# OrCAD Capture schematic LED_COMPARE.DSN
size C
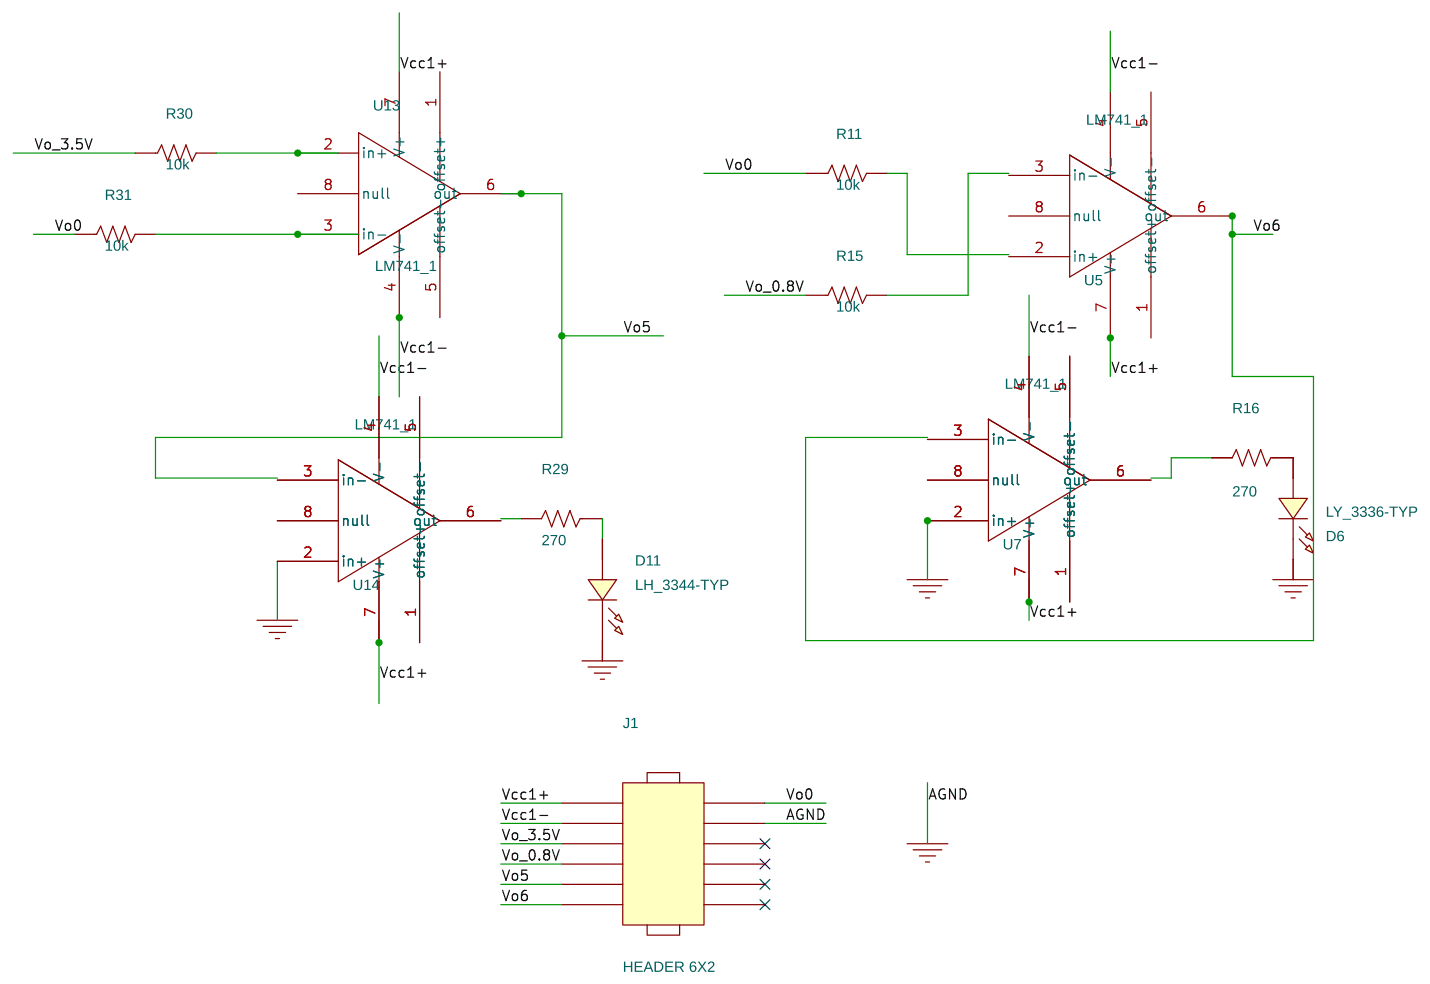
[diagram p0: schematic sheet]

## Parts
D6  LY_3336-TYP  [fg]
D11  LH_3344-TYP  [fg]
J1  HEADER 6X2  [dip20_6]
R11  10k  [0805]
R15  10k  [0805]
R16  270  [0805]
R29  270  [0805]
R30  10k  [0805]
R31  10k  [0805]
U5  LM741_1  [soic8]
U7  LM741_1  [soic8]
U13  LM741_1  [soic8]
U14  LM741_1  [soic8]

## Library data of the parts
D6 = LY_3336-TYP
D11 = LH_3344-TYP
J1 = HEADER_6X2
R11 R15 R16 R29-R31 = R
U5 U7 U13 U14 = LM741_1

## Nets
Vcc1+: J1.2 U5.7(V+) U7.7(V+) U13.7(V+) U14.7(V+)
Vcc1-: J1.4 U5.4(V-) U7.4(V-) U13.4(V-) U14.4(V-)
0: D6.2 D11.2 J1.3 U7.2(in+) U14.2(in+)
Vo0: J1.1 R11.1 R31.1
Vo5: J1.10 U13.6(out)
Vo6: J1.12 U5.6(out)
Vo_0.8V: J1.8 R15.1
Vo_3.5V: J1.6 R30.1
N181986: R30.2 U13.2(in+)
N181992: R31.2 U13.3(in-)
N184618: D6.1 R16.1
N184634: D11.1 R29.1

Not connected (* = marked no-connect by the designer): J1 5* 7* 9* 11*; R11 2; R15 2; R16 2; R29 2; U5 1(offset+) 2(in+) 3(in-) 5(offset-) 8(null); U7 1(offset+) 3(in-) 5(offset-) 6(out) 8(null); U13 1(offset+) 5(offset-) 8(null); U14 1(offset+) 3(in-) 5(offset-) 6(out) 8(null)
